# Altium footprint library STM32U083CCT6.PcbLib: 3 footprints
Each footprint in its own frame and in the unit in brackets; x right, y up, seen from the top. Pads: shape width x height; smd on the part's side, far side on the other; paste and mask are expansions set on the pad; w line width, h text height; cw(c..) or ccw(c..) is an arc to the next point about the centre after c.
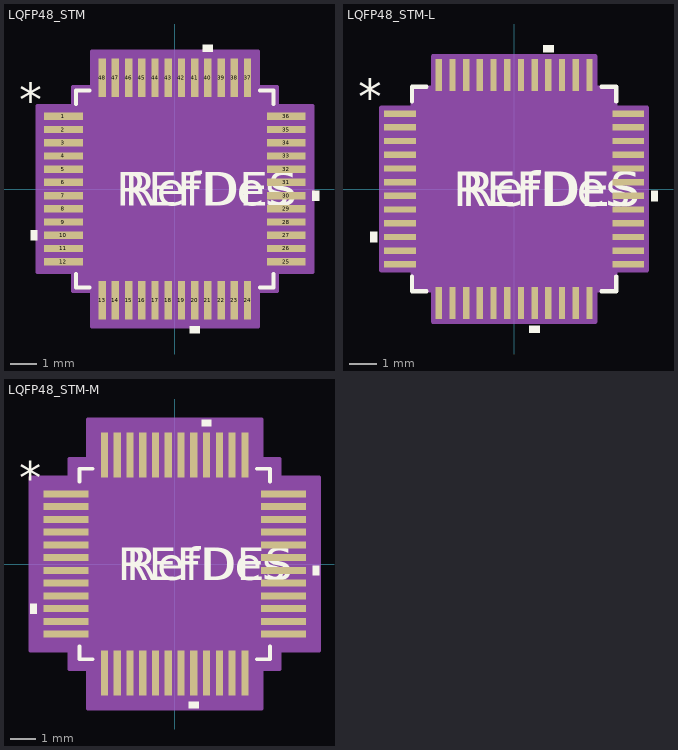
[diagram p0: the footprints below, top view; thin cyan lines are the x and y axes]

## LQFP48_STM [mil]
pads (48):
  rect 57.56x11 smd paste+0 mask+0: 1(-166,108.27) 2(-166,88.58) 3(-166,68.9) 4(-166,49.21) 5(-166,29.53) 6(-166,9.84) 7(-166,-9.84) 8(-166,-29.53) 9(-166,-49.21) 10(-166,-68.9) 11(-166,-88.58) 12(-166,-108.27) 25(166,-108.27) 26(166,-88.58) 27(166,-68.9) 28(166,-49.21) 29(166,-29.53) 30(166,-9.84) 31(166,9.84) 32(166,29.53) 33(166,49.21) 34(166,68.9) 35(166,88.58) 36(166,108.27)
  rect 11x57.56 smd paste+0 mask+0: 13(-108.27,-166) 14(-88.58,-166) 15(-68.9,-166) 16(-49.21,-166) 17(-29.53,-166) 18(-9.84,-166) 19(9.84,-166) 20(29.53,-166) 21(49.21,-166) 22(68.9,-166) 23(88.58,-166) 24(108.27,-166) 37(108.27,166) 38(88.58,166) 39(68.9,166) 40(49.21,166) 41(29.53,166) 42(9.84,166) 43(-9.84,166) 44(-29.53,166) 45(-49.21,166) 46(-68.9,166) 47(-88.58,166) 48(-108.27,166)
Top Overlay:
  region: -204.78,-61.4 -214.78,-61.4 -214.78,-76.4 -204.78,-76.4
  region: 37.03,-204.78 22.03,-204.78 22.03,-214.78 37.03,-214.78
  region: 204.78,-2.34 214.78,-2.34 214.78,-17.34 204.78,-17.34
  region: 56.71,204.78 41.71,204.78 41.71,214.78 56.71,214.78
  lines w6: -147,-126.87 -147,-147 -126.87,-147 ; -147,126.87 -147,147 -126.87,147 ; 126.87,-147 147,-147 147,-126.87 ; 126.87,147 147,147 147,126.87
  text "*" at -232.28,108.11 h50
  text "RefDes" at -75,-25 h50
  text "REFDES" at -87.5,-25 h50
Mechanical 13:
  drawing of 197 lines, arcs and shapes, not listed
  text "*" at -139.5,93.11 h50
  text "RefDes2" at -87.5,-25 h50
Mechanical 15:
  region: -123.77,-152 -152,-152 -152,-123.77 -204.78,-123.77 -204.78,123.77 -152,123.77 -152,152 -123.77,152 -123.77,204.78 123.77,204.78 123.77,152 152,152 152,123.77 204.78,123.77 204.78,-123.77 152,-123.77 152,-152 123.77,-152 123.77,-204.78 -123.77,-204.78
  lines w6: -204.78,-123.77 -152,-123.77 -152,-152 -123.77,-152 -123.77,-204.78 123.77,-204.78 123.77,-152 152,-152 152,-123.77 204.78,-123.77 204.78,123.77 152,123.77 152,152 123.77,152 123.77,204.78 -123.77,204.78 -123.77,152 -152,152 -152,123.77 -204.78,123.77 -204.78,-123.77
3D body "LQFP48_STM.step": height 63.11, standoff 0, extent -180.98,-180.98 180.98,180.98

## LQFP48_STM-L [mm]
pads (48):
  rect 1.162x0.229 smd paste+0 mask+0: 1(-4.166,2.75) 2(-4.166,2.25) 3(-4.166,1.75) 4(-4.166,1.25) 5(-4.166,0.75) 6(-4.166,0.25) 7(-4.166,-0.25) 8(-4.166,-0.75) 9(-4.166,-1.25) 10(-4.166,-1.75) 11(-4.166,-2.25) 12(-4.166,-2.75) 25(4.166,-2.75) 26(4.166,-2.25) 27(4.166,-1.75) 28(4.166,-1.25) 29(4.166,-0.75) 30(4.166,-0.25) 31(4.166,0.25) 32(4.166,0.75) 33(4.166,1.25) 34(4.166,1.75) 35(4.166,2.25) 36(4.166,2.75)
  rect 0.229x1.162 smd paste+0 mask+0: 13(-2.75,-4.166) 14(-2.25,-4.166) 15(-1.75,-4.166) 16(-1.25,-4.166) 17(-0.75,-4.166) 18(-0.25,-4.166) 19(0.25,-4.166) 20(0.75,-4.166) 21(1.25,-4.166) 22(1.75,-4.166) 23(2.25,-4.166) 24(2.75,-4.166) 37(2.75,4.166) 38(2.25,4.166) 39(1.75,4.166) 40(1.25,4.166) 41(0.75,4.166) 42(0.25,4.166) 43(-0.25,4.166) 44(-0.75,4.166) 45(-1.25,4.166) 46(-1.75,4.166) 47(-2.25,4.166) 48(-2.75,4.166)
Top Overlay:
  region: -5.001,-1.559 -5.255,-1.559 -5.255,-1.94 -5.001,-1.94
  region: 0.941,-5.001 0.56,-5.001 0.56,-5.255 0.941,-5.255
  region: 5.001,-0.059 5.255,-0.059 5.255,-0.44 5.001,-0.44
  region: 1.441,5.001 1.06,5.001 1.06,5.255 1.441,5.255
  lines w0.152: -3.734,-3.197 -3.734,-3.734 -3.197,-3.734 ; -3.734,3.197 -3.734,3.734 -3.197,3.734 ; 3.197,-3.734 3.734,-3.734 3.734,-3.197 ; 3.197,3.734 3.734,3.734 3.734,3.197
  text "*" at -5.7,2.746 h1.27
  text "RefDes" at -1.905,-0.635 h1.27
  text "REFDES" at -2.222,-0.635 h1.27
Mechanical 13:
  drawing of 197 lines, arcs and shapes, not listed
  text "*" at -3.543,2.365 h1.27
  text "RefDes2" at -2.222,-0.635 h1.27
Mechanical 15:
  region: -2.966,-3.708 -3.708,-3.708 -3.708,-2.966 -4.849,-2.966 -4.849,2.966 -3.708,2.966 -3.708,3.708 -2.966,3.708 -2.966,4.849 2.966,4.849 2.966,3.708 3.708,3.708 3.708,2.966 4.849,2.966 4.849,-2.966 3.708,-2.966 3.708,-3.708 2.966,-3.708 2.966,-4.849 -2.966,-4.849
  lines w0.152: -4.849,-2.966 -3.708,-2.966 -3.708,-3.708 -2.966,-3.708 -2.966,-4.849 2.966,-4.849 2.966,-3.708 3.708,-3.708 3.708,-2.966 4.849,-2.966 4.849,2.966 3.708,2.966 3.708,3.708 2.966,3.708 2.966,4.849 -2.966,4.849 -2.966,3.708 -3.708,3.708 -3.708,2.966 -4.849,2.966 -4.849,-2.966
3D body "LQFP48_STM.step": height 1.6, standoff 0, extent -4.597,-4.597 4.597,4.597

## LQFP48_STM-M [mm]
pads (48):
  rect 1.762x0.279 smd paste+0 mask+0: 1(-4.266,2.75) 2(-4.266,2.25) 3(-4.266,1.75) 4(-4.266,1.25) 5(-4.266,0.75) 6(-4.266,0.25) 7(-4.266,-0.25) 8(-4.266,-0.75) 9(-4.266,-1.25) 10(-4.266,-1.75) 11(-4.266,-2.25) 12(-4.266,-2.75) 25(4.266,-2.75) 26(4.266,-2.25) 27(4.266,-1.75) 28(4.266,-1.25) 29(4.266,-0.75) 30(4.266,-0.25) 31(4.266,0.25) 32(4.266,0.75) 33(4.266,1.25) 34(4.266,1.75) 35(4.266,2.25) 36(4.266,2.75)
  rect 0.279x1.762 smd paste+0 mask+0: 13(-2.75,-4.266) 14(-2.25,-4.266) 15(-1.75,-4.266) 16(-1.25,-4.266) 17(-0.75,-4.266) 18(-0.25,-4.266) 19(0.25,-4.266) 20(0.75,-4.266) 21(1.25,-4.266) 22(1.75,-4.266) 23(2.25,-4.266) 24(2.75,-4.266) 37(2.75,4.266) 38(2.25,4.266) 39(1.75,4.266) 40(1.25,4.266) 41(0.75,4.266) 42(0.25,4.266) 43(-0.25,4.266) 44(-0.75,4.266) 45(-1.25,4.266) 46(-1.75,4.266) 47(-2.25,4.266) 48(-2.75,4.266)
Top Overlay:
  region: -5.401,-1.559 -5.655,-1.559 -5.655,-1.94 -5.401,-1.94
  region: 0.941,-5.401 0.56,-5.401 0.56,-5.655 0.941,-5.655
  region: 5.401,-0.059 5.655,-0.059 5.655,-0.44 5.401,-0.44
  region: 1.441,5.401 1.06,5.401 1.06,5.655 1.441,5.655
  lines w0.152: -3.734,-3.222 -3.734,-3.734 -3.222,-3.734 ; -3.734,3.222 -3.734,3.734 -3.222,3.734 ; 3.222,-3.734 3.734,-3.734 3.734,-3.222 ; 3.222,3.734 3.734,3.734 3.734,3.222
  text "*" at -6.1,2.746 h1.27
  text "RefDes" at -1.905,-0.635 h1.27
  text "REFDES" at -2.222,-0.635 h1.27
Mechanical 13:
  drawing of 197 lines, arcs and shapes, not listed
  text "*" at -3.543,2.365 h1.27
  text "RefDes2" at -2.222,-0.635 h1.27
Mechanical 15:
  region: -3.398,-4.115 -4.115,-4.115 -4.115,-3.398 -5.655,-3.398 -5.655,3.398 -4.115,3.398 -4.115,4.115 -3.398,4.115 -3.398,5.655 3.398,5.655 3.398,4.115 4.115,4.115 4.115,3.398 5.655,3.398 5.655,-3.398 4.115,-3.398 4.115,-4.115 3.398,-4.115 3.398,-5.655 -3.398,-5.655
  lines w0.152: -5.655,-3.398 -4.115,-3.398 -4.115,-4.115 -3.398,-4.115 -3.398,-5.655 3.398,-5.655 3.398,-4.115 4.115,-4.115 4.115,-3.398 5.655,-3.398 5.655,3.398 4.115,3.398 4.115,4.115 3.398,4.115 3.398,5.655 -3.398,5.655 -3.398,4.115 -4.115,4.115 -4.115,3.398 -5.655,3.398 -5.655,-3.398
3D body "LQFP48_STM.step": height 1.6, standoff 0, extent -4.597,-4.597 4.597,4.597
